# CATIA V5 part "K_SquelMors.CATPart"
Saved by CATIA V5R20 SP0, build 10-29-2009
Part number: Squelette_mors
Publications: "Axe_pivot_mors_1", "Axe_pivot_mors_2"
Bounding box of the stored display mesh (mm): x -650.011 to -400.011, y 5 to 45, z -182.717 to 177.283
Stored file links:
  G:\Khaled_CFAO_2011\ST2M\ST2M_GR2\jcoetard\Khaled\CAD_CATIA\K_SquelMors.CATPart
  G:\Khaled_CFAO_2011\ST2M\ST2M_GR2\jcoetard\Khaled\CAD_CATIA\K_Squelette.CATProduct
  G:\Khaled_CFAO_2011\ST2M\ST2M_GR2\jcoetard\jcoetard\Maquette_jcoetard\Squelette General.CATPart
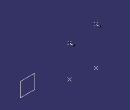
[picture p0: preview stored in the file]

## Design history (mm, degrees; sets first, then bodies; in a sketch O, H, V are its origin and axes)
Set1
  Plane1 "Plan_Ref": linked copy from another document
  Point1: linked copy from another document
  Point2: linked copy from another document
  Point3 "Point.9": linked copy from another document
  Point4 "Point.10": linked copy from another document
Set2 "Set géométrique"
  Line1 "Axe_pivot_mors_1": type Normal, RefPoint Point1, RefSkin Plane1, Start 0, End 40
  Line2 "Axe_pivot_mors_2": type Normal, RefPoint Point2, RefSkin Plane1, Start 0, End 40
Body1 (main body)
